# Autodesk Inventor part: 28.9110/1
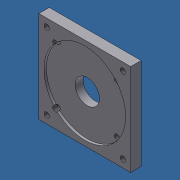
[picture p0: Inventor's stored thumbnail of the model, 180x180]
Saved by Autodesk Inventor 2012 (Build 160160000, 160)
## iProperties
Created: 2008-03
Part Number: 28.9110/1
Document SubType Name: Modeling
Designer: Andy Moles
Density: 2.71 g/cm^3
Mass: 143.158 g
Surface Area: 182.54 cm^2
Volume: 52.8258 cm^3
Material: Aluminum-6061
Description: MACHINE TO 28.9110/1
Stock Number: 20.9313 AL BARSTOCK 3/8" X 3.5"
Vendor: F
Author: Andy Moles
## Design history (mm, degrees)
sketch "Sketch1"
  geometry: L1 (-72.099, 48.471)-(11.721, 48.471); L2 (11.721, 48.471)-(11.721, -35.349); L3 (11.721, -35.349)-(-72.099, -35.349); L4 (-72.099, -35.349)-(-72.099, 48.471); C1 r 2.387 at (-57.189, 32.561); C2 r 2.387 at (-3.189, 29.061); C3 r 2.387 at (-3.189, -15.939); C4 r 2.387 at (-57.189, -19.439); C5 r 11.113 at (-30.189, 6.561); C6 r 3 at (-57.189, 32.561); C7 r 3 at (-3.189, 29.061); C8 r 3 at (-3.189, -15.939); C9 r 3 at (-57.189, -19.439); A1 r 6.35 centre (-30.189, 6.561) between (-31.777, 12.709) and (-28.602, 12.709); 3 further points
  constraints: 10 centre point, 8 end point, 5 coincident, 2 midpoint, 2 parallel, 2 perpendicular, 2 point on circle, 1 horizontal, 1 horizontal alignment, 1 vertical alignment
  dimensions: "d0" = 22.225 diameter of C5; "d1" = 83.82 distance of L1.start L1.end; "d16" = 6 diameter of C6; "d17" = 6 diameter of C9; "d18" = 6 diameter of C8; "d19" = 6 diameter of C7
extrude "Extrusion1" new body sketch "Sketch1" distance "d2" = 9.525; taper "d3" = 0 deg
sketch "Sketch2"
  geometry: C1 r 11.112 at (-30.189, 6.561) reference; C2 r 37.306 at (-30.189, 6.561); 1 further point
  constraints: 1 centre point, 1 coincident
  dimensions: "d4" = 74.6125 diameter of C2
extrude "Extrusion2" cut sketch "Sketch2" distance "d5" = 2.286; taper "d6" = 0 deg
sketch "Sketch3"
  geometry: C1 r 2.769 at (-64.988, 41.359); C2 r 2.769 at (4.609, 41.359); C3 r 2.769 at (-64.988, -28.238); C4 r 2.769 at (4.609, -28.238); 5 further points
  constraints: 4 centre point, 4 coincident
hole "Hole1" sketch "Sketch3" at (-64.988, 41.359), (4.609, 41.359), (-64.988, -28.238), (4.609, -28.238) diameter "d9" = 4.9276; stored, may be unused: countersink angle "d13" = 82 deg, drill point angle "d15" = 118 deg; dims "d10" = 12.7, "d11" = 9.525, "d12" = 6.35, "d14" = 19.05
thread "Thread5" dims "d28" = 25.4, "d29" = 0
thread "Thread6" dims "d30" = 25.4, "d31" = 0
thread "Thread7" dims "d32" = 25.4, "d33" = 0
thread "Thread8" dims "d34" = 25.4, "d35" = 0
body "Solid1"
